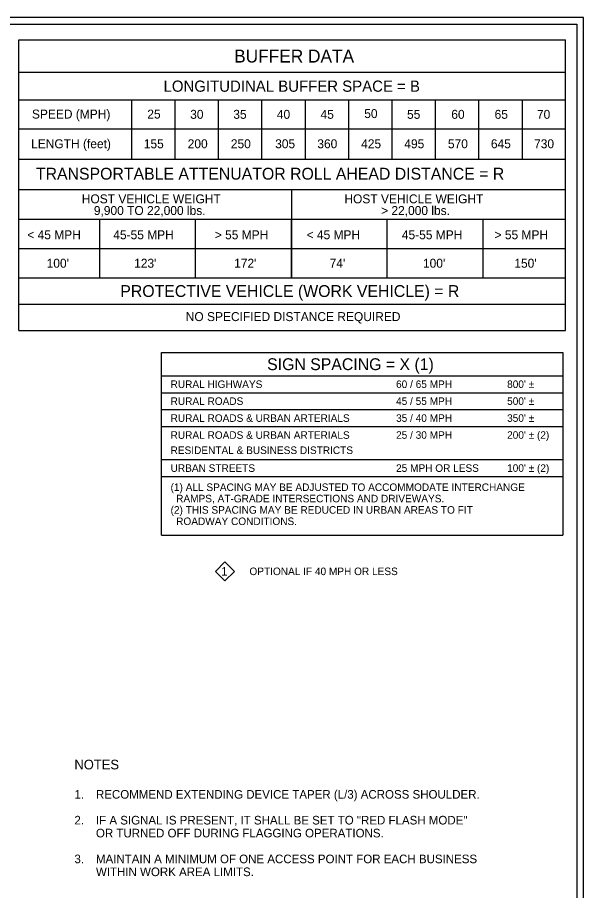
# Model space of a CAD drawing. Extents: x 99988 to 100172, y 99995 to 100047.
# Drawn here: x 100010.55 to 100015.81, y 100002.32 to 100010.44 of the extents above; entities that cross this region are included whole.
import ezdxf

# ---------------------------------------------------------------- set-up
doc = ezdxf.new("R2010")
doc.units = 0
for name, color, linetype in [('Level 20', 7, 'Continuous'), ('SH_DE_DetailBody1Text', 7, 'Continuous'), ('SH_GI_PlotLimits', 7, 'Continuous'), ('SH_GI_SheetBorder', 7, 'Continuous'), ('SH_TI_BufferDataNote', 7, 'Continuous'), ('SH_TI_SignSpacing35to70Note', 7, 'Continuous')]:
    doc.layers.add(name, color=color, linetype=linetype)

msp = doc.modelspace()

# ---------------------------------------------------------------- linework, layer by layer
at = {"layer": 'SH_DE_DetailBody1Text'}
msp.add_lwpolyline([(100012.4799, 100005.3775), (100012.5677, 100005.2897), (100012.4799, 100005.2019), (100012.3922, 100005.2897)], close=True, dxfattribs=at)
at = {"layer": 'SH_GI_PlotLimits'}
msp.add_lwpolyline([(99999.3125, 99999.9375), (100015.8125, 99999.9375), (100015.8125, 100010.4375), (99999.3125, 100010.4375)], close=True, dxfattribs=at)
at = {"layer": 'SH_GI_SheetBorder'}
for p, q in [((100000, 100010.375), (100015.75, 100010.375)), ((100015.75, 100010.375), (100015.75, 100000))]:
    msp.add_line(p, q, dxfattribs=at)
at = {"layer": 'SH_TI_BufferDataNote'}
for p, q in [((100010.5644, 100010.2311), (100015.6446, 100010.2311)), ((100010.5644, 100007.5274), (100010.5644, 100010.2311)), ((100015.6446, 100007.5274), (100015.6446, 100010.2311)), ((100010.5644, 100009.9279), (100015.6446, 100009.9279)), ((100010.5644, 100009.6733), (100015.6446, 100009.6733)), ((100011.6103, 100009.6733), (100011.6103, 100009.1216)), ((100012.0138, 100009.6733), (100012.0138, 100009.1216)), ((100012.4172, 100009.6733), (100012.4172, 100009.1216)), ((100012.8206, 100009.6733), (100012.8206, 100009.1216)), ((100013.224, 100009.6733), (100013.224, 100009.1216)), ((100013.6274, 100009.6733), (100013.6274, 100009.1216)), ((100014.0309, 100009.6733), (100014.0309, 100009.1216)), ((100014.4343, 100009.6733), (100014.4343, 100009.1216)), ((100014.8377, 100009.6733), (100014.8377, 100009.1216)), ((100015.2411, 100009.6733), (100015.2411, 100009.1216)), ((100010.5644, 100009.4038), (100015.6446, 100009.4038)), ((100010.5644, 100009.1216), (100015.6446, 100009.1216)), ((100010.5644, 100008.8373), (100015.6446, 100008.8373)), ((100013.1018, 100008.0177), (100013.1018, 100008.8351)), ((100010.5644, 100008.5641), (100015.6446, 100008.5641)), ((100011.3157, 100008.0176), (100011.3157, 100008.5641)), ((100012.2067, 100008.0176), (100012.2067, 100008.5641)), ((100013.0977, 100008.0176), (100013.0977, 100008.5641)), ((100013.9887, 100008.0176), (100013.9887, 100008.5641)), ((100014.8797, 100008.0176), (100014.8797, 100008.5641)), ((100010.5644, 100008.2908), (100015.6446, 100008.2908)), ((100010.5644, 100008.0176), (100015.6446, 100008.0176)), ((100010.5644, 100007.7725), (100015.6446, 100007.7725)), ((100010.5644, 100007.5274), (100015.6446, 100007.5274))]:
    msp.add_line(p, q, dxfattribs=at)
at = {"layer": 'SH_TI_SignSpacing35to70Note'}
for p, q in [((100011.8909, 100007.1076), (100015.6192, 100007.1076)), ((100011.8909, 100006.9502), (100015.6192, 100006.9502)), ((100011.8909, 100006.7928), (100015.6192, 100006.7928)), ((100011.8909, 100006.6354), (100015.6192, 100006.6354)), ((100011.8909, 100006.328), (100015.6192, 100006.328)), ((100011.8909, 100006.1705), (100015.6192, 100006.1705)), ((100011.8909, 100005.6269), (100015.6192, 100005.6269))]:
    msp.add_line(p, q, dxfattribs=at)
for points in [[(100011.8909, 100005.6269), (100011.8909, 100007.3222)], [(100011.8909, 100007.3222), (100015.6192, 100007.3222), (100015.6192, 100007.1076)], [(100015.6192, 100007.1076), (100015.6192, 100005.6269)]]:
    msp.add_lwpolyline(points, dxfattribs=at)

# ---------------------------------------------------------------- texts
at = {"layer": 'Level 20'}
for s, height, p in [('NOTES', 0.09, (100011.081, 100003.4489)), ('1.', 0.08, (100011.081, 100003.1769)), ('RECOMMEND EXTENDING DEVICE TAPER (L/3) ACROSS SHOULDER.', 0.08, (100011.281, 100003.1769)), ('2.', 0.08, (100011.081, 100002.9369)), ('IF A SIGNAL IS PRESENT, IT SHALL BE SET TO "RED FLASH MODE"', 0.08, (100011.281, 100002.9369)), ('OR TURNED OFF DURING FLAGGING OPERATIONS.', 0.08, (100011.281, 100002.8169)), ('3.', 0.08, (100011.081, 100002.5769)), ('MAINTAIN A MINIMUM OF ONE ACCESS POINT FOR EACH BUSINESS', 0.08, (100011.281, 100002.5769)), ('WITHIN WORK AREA LIMITS.', 0.08, (100011.281, 100002.4569))]:
    msp.add_text(s, height=height, dxfattribs=at).set_placement(p)
at = {"layer": 'SH_DE_DetailBody1Text'}
for s, height, p in [('1', 0.08, (100012.4448, 100005.2497)), ('OPTIONAL IF 40 MPH OR LESS', 0.07, (100012.7077, 100005.2547))]:
    msp.add_text(s, height=height, dxfattribs=at).set_placement(p)
at = {"layer": 'SH_TI_BufferDataNote'}
for s, height, p in [('BUFFER DATA', 0.12, (100012.5656, 100010.0185)), ('LONGITUDINAL BUFFER SPACE = B', 0.10395, (100011.9093, 100009.747)), ('SPEED (MPH)', 0.08316, (100010.6861, 100009.4979)), ('25', 0.08316, (100011.7584, 100009.4979)), ('30', 0.08316, (100012.1569, 100009.4955)), ('35', 0.08316, (100012.5576, 100009.4955)), ('40', 0.08316, (100012.9623, 100009.4955)), ('45', 0.08316, (100013.3684, 100009.4955)), ('50', 0.08316, (100013.7745, 100009.5026)), ('55', 0.08316, (100014.1722, 100009.4955)), ('60', 0.08316, (100014.5836, 100009.4955)), ('65', 0.08316, (100014.986, 100009.4955)), ('70', 0.08316, (100015.3795, 100009.4955)), ('LENGTH (feet)', 0.08316, (100010.6786, 100009.222)), ('155', 0.08316, (100011.7256, 100009.222)), ('200', 0.08316, (100012.1338, 100009.222)), ('250', 0.08316, (100012.5347, 100009.222)), ('305', 0.08316, (100012.9466, 100009.222)), ('360', 0.08316, (100013.3386, 100009.222)), ('425', 0.08316, (100013.7456, 100009.222)), ('495', 0.08316, (100014.1468, 100009.222)), ('570', 0.08316, (100014.5521, 100009.222)), ('645', 0.08316, (100014.9514, 100009.222)), ('730', 0.08316, (100015.353, 100009.222)), ('TRANSPORTABLE ATTENUATOR ROLL AHEAD DISTANCE = R', 0.11, (100010.7232, 100008.9304)), ('HOST VEHICLE WEIGHT', 0.08316, (100011.1496, 100008.71)), ('HOST VEHICLE WEIGHT', 0.08316, (100013.5901, 100008.71)), ('9,900 TO 22,000 lbs.', 0.08316, (100011.2614, 100008.6017)), ('> 22,000 lbs.', 0.08316, (100013.9311, 100008.6017)), ('< 45 MPH', 0.08316, (100010.643, 100008.3762)), ('45-55 MPH', 0.08316, (100011.4422, 100008.3762)), ('> 55 MPH', 0.08316, (100012.3853, 100008.3762)), ('< 45 MPH', 0.08316, (100013.2387, 100008.3762)), ('45-55 MPH', 0.08316, (100014.124, 100008.3762)), ('> 55 MPH', 0.08316, (100014.9856, 100008.3762)), ("100'", 0.08316, (100010.823, 100008.1116)), ("123'", 0.08316, (100011.6359, 100008.1116)), ("172'", 0.08316, (100012.5653, 100008.1116)), ("74'", 0.08316, (100013.453, 100008.1116)), ("100'", 0.08316, (100014.3205, 100008.1116)), ("150'", 0.08316, (100015.1695, 100008.1116)), ('PROTECTIVE VEHICLE (WORK VEHICLE) = R', 0.11, (100011.5074, 100007.8396)), ('NO SPECIFIED DISTANCE REQUIRED', 0.08316, (100012.1155, 100007.6156))]:
    msp.add_text(s, height=height, dxfattribs=at).set_placement(p)
at = {"layer": 'SH_TI_SignSpacing35to70Note'}
for s, height, p in [('SIGN SPACING = X (1)', 0.11, (100012.8718, 100007.1599)), ('RURAL HIGHWAYS', 0.07, (100011.9747, 100006.9939)), ('60 / 65 MPH', 0.07, (100014.0703, 100006.9939)), ("800' ±", 0.07, (100015.1023, 100006.9939)), ('RURAL ROADS', 0.07, (100011.9747, 100006.8365)), ('45 / 55 MPH', 0.07, (100014.0703, 100006.8365)), ("500' ±", 0.07, (100015.1023, 100006.8365)), ('RURAL ROADS & URBAN ARTERIALS', 0.07, (100011.9747, 100006.6791)), ('35 / 40 MPH', 0.07, (100014.0703, 100006.6791)), ("350' ± ", 0.07, (100015.1023, 100006.6791)), ('RURAL ROADS & URBAN ARTERIALS', 0.07, (100011.9747, 100006.5214)), ('25 / 30 MPH', 0.07, (100014.0703, 100006.5217)), ("200' ± (2)", 0.07, (100015.1023, 100006.5217)), ('RESIDENTAL & BUSINESS DISTRICTS', 0.07, (100011.9747, 100006.3803)), ('URBAN STREETS', 0.07, (100011.9747, 100006.2143)), ('25 MPH OR LESS', 0.07, (100014.0703, 100006.2143)), ("100' ± (2) ", 0.07, (100015.1023, 100006.2143)), ('(1) ALL SPACING MAY BE ADJUSTED TO ACCOMMODATE INTERCHANGE ', 0.07, (100011.9746, 100006.0366)), ('  RAMPS, AT-GRADE INTERSECTIONS AND DRIVEWAYS.', 0.07, (100011.9746, 100005.9311)), ('(2) THIS SPACING MAY BE REDUCED IN URBAN AREAS TO FIT  ', 0.07, (100011.9746, 100005.8255)), ('  ROADWAY CONDITIONS.', 0.07, (100011.9746, 100005.7199))]:
    msp.add_text(s, height=height, dxfattribs=at).set_placement(p)

doc.saveas('drawing.dxf')
